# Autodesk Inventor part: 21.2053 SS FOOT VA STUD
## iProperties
Created: 2011-11
Part Number: 21.2053 SS FOOT VA STUD
Material: Stainless Steel
Document SubType Name: Modeling
Designer: Administrator
Mass: 19.1541 g
Surface Area: 19.5564 cm^2
Volume: 2.37056 cm^3
Density: 8.08 g/cm^3
Author: Administrator
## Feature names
1. Base1
